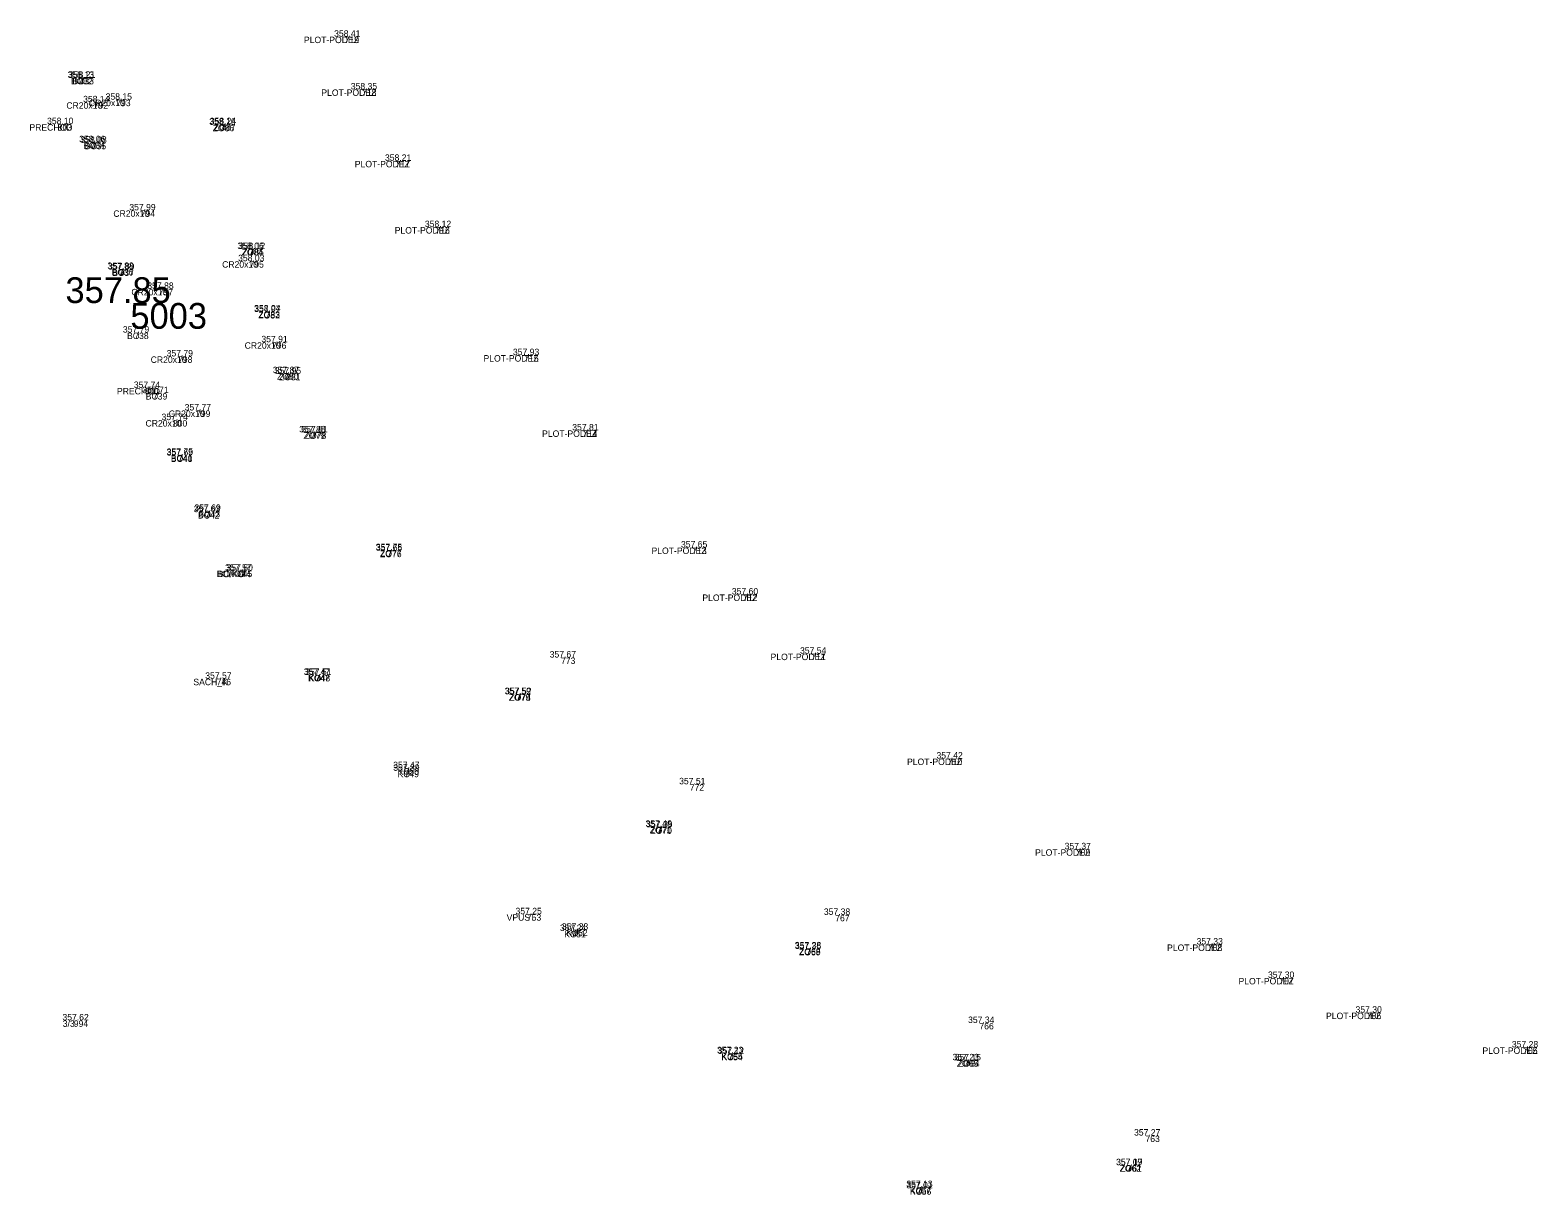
# Model space of a CAD drawing. Extents: x -590413 to -590216, y -1129419 to -1129249.
# Drawn here: x -590268.51 to -590245.08, y -1129323.66 to -1129305.56 of the extents above; entities that cross this region are included whole.
import ezdxf

# ---------------------------------------------------------------- set-up
doc = ezdxf.new("R2010")
doc.units = 0
for name, color, linetype in [('Vrstva B24', 7, 'Continuous'), ('Vrstva B54', 7, 'Continuous'), ('Vrstva B55', 7, 'Continuous'), ('Vrstva B56', 7, 'Continuous'), ('Vrstva B58', 7, 'Continuous'), ('Vrstva B59', 7, 'Continuous'), ('Vrstva B60', 7, 'Continuous')]:
    doc.layers.add(name, color=color, linetype=linetype)

msp = doc.modelspace()

# ---------------------------------------------------------------- linework, layer by layer
at = {"layer": 'Vrstva B56'}
msp.add_line((-590266.95, -1129309.8), (-590266.95, -1129309.8), dxfattribs=at)
at = {"layer": 'Vrstva B60'}
for p, q in [((-590263.62, -1129305.66), (-590263.62, -1129305.66)), ((-590267.76, -1129306.3), (-590267.76, -1129306.3)), ((-590267.74, -1129306.3), (-590267.74, -1129306.3)), ((-590263.35, -1129306.48), (-590263.35, -1129306.48)), ((-590267.52, -1129306.68), (-590267.52, -1129306.68)), ((-590267.17, -1129306.64), (-590267.17, -1129306.64)), ((-590268.08, -1129307.02), (-590268.08, -1129307.02)), ((-590265.56, -1129307.03), (-590265.56, -1129307.03)), ((-590265.54, -1129307.02), (-590265.54, -1129307.02)), ((-590267.57, -1129307.3), (-590267.57, -1129307.3)), ((-590267.55, -1129307.31), (-590267.55, -1129307.31)), ((-590262.83, -1129307.59), (-590262.83, -1129307.59)), ((-590266.79, -1129308.36), (-590266.79, -1129308.36)), ((-590262.21, -1129308.62), (-590262.21, -1129308.62)), ((-590265.11, -1129308.96), (-590265.11, -1129308.96)), ((-590265.1, -1129308.96), (-590265.1, -1129308.96)), ((-590265.1, -1129309.15), (-590265.1, -1129309.15)), ((-590267.13, -1129309.27), (-590267.13, -1129309.27)), ((-590267.12, -1129309.28), (-590267.12, -1129309.28)), ((-590266.51, -1129309.58), (-590266.51, -1129309.58)), ((-590264.85, -1129309.93), (-590264.85, -1129309.93)), ((-590264.85, -1129309.94), (-590264.85, -1129309.94)), ((-590266.89, -1129310.26), (-590266.89, -1129310.26)), ((-590264.75, -1129310.41), (-590264.75, -1129310.41)), ((-590266.21, -1129310.63), (-590266.21, -1129310.63)), ((-590260.83, -1129310.61), (-590260.83, -1129310.61)), ((-590264.56, -1129310.89), (-590264.56, -1129310.89)), ((-590264.53, -1129310.9), (-590264.53, -1129310.9)), ((-590266.72, -1129311.12), (-590266.72, -1129311.12)), ((-590266.6, -1129311.2), (-590266.6, -1129311.2)), ((-590265.93, -1129311.47), (-590265.93, -1129311.47)), ((-590266.29, -1129311.62), (-590266.29, -1129311.62)), ((-590264.15, -1129311.81), (-590264.15, -1129311.81)), ((-590264.13, -1129311.81), (-590264.13, -1129311.81)), ((-590259.92, -1129311.78), (-590259.92, -1129311.78)), ((-590266.21, -1129312.16), (-590266.21, -1129312.16)), ((-590266.21, -1129312.17), (-590266.21, -1129312.17)), ((-590265.79, -1129313.05), (-590265.79, -1129313.05)), ((-590265.78, -1129313.03), (-590265.78, -1129313.03)), ((-590258.22, -1129313.6), (-590258.22, -1129313.6)), ((-590262.96, -1129313.64), (-590262.96, -1129313.64)), ((-590262.96, -1129313.65), (-590262.96, -1129313.65)), ((-590265.3, -1129313.96), (-590265.3, -1129313.96)), ((-590265.28, -1129313.96), (-590265.28, -1129313.96)), ((-590257.43, -1129314.33), (-590257.43, -1129314.33)), ((-590260.26, -1129315.31), (-590260.26, -1129315.31)), ((-590256.37, -1129315.25), (-590256.37, -1129315.25)), ((-590265.61, -1129315.64), (-590265.61, -1129315.64)), ((-590264.08, -1129315.58), (-590264.08, -1129315.58)), ((-590264.07, -1129315.58), (-590264.07, -1129315.58)), ((-590260.96, -1129315.88), (-590260.96, -1129315.88)), ((-590260.95, -1129315.88), (-590260.95, -1129315.88)), ((-590254.25, -1129316.88), (-590254.25, -1129316.88)), ((-590262.69, -1129317.03), (-590262.69, -1129317.03)), ((-590262.69, -1129317.07), (-590262.69, -1129317.07)), ((-590258.26, -1129317.28), (-590258.26, -1129317.28)), ((-590258.77, -1129317.94), (-590258.77, -1129317.94)), ((-590258.76, -1129317.95), (-590258.76, -1129317.95)), ((-590252.26, -1129318.29), (-590252.26, -1129318.29)), ((-590260.79, -1129319.3), (-590260.79, -1129319.3)), ((-590256, -1129319.31), (-590256, -1129319.31)), ((-590260.1, -1129319.56), (-590260.1, -1129319.56)), ((-590260.07, -1129319.54), (-590260.07, -1129319.54)), ((-590256.45, -1129319.83), (-590256.45, -1129319.83)), ((-590256.45, -1129319.84), (-590256.45, -1129319.84)), ((-590250.21, -1129319.77), (-590250.21, -1129319.77)), ((-590249.1, -1129320.29), (-590249.1, -1129320.29)), ((-590247.74, -1129320.83), (-590247.74, -1129320.83)), ((-590267.83, -1129320.95), (-590267.83, -1129320.95)), ((-590253.76, -1129320.99), (-590253.76, -1129320.99)), ((-590257.66, -1129321.46), (-590257.66, -1129321.46)), ((-590257.66, -1129321.47), (-590257.66, -1129321.47)), ((-590245.31, -1129321.37), (-590245.31, -1129321.37)), ((-590254, -1129321.57), (-590254, -1129321.57)), ((-590253.98, -1129321.57), (-590253.98, -1129321.57)), ((-590251.18, -1129322.74), (-590251.18, -1129322.74)), ((-590251.47, -1129323.2), (-590251.47, -1129323.2)), ((-590251.46, -1129323.2), (-590251.46, -1129323.2)), ((-590254.73, -1129323.54), (-590254.73, -1129323.54)), ((-590254.73, -1129323.56), (-590254.73, -1129323.56))]:
    msp.add_line(p, q, dxfattribs=at)

# ---------------------------------------------------------------- texts
at = {"layer": 'Vrstva B24'}
for s, p in [('PLOT-PODEZ', (-590264.254, -1129305.76)), ('BO', (-590267.872, -1129306.4)), ('BO', (-590267.852, -1129306.4)), ('PLOT-PODEZ', (-590263.984, -1129306.58)), ('CR20x10', (-590267.945, -1129306.78)), ('CR20x10', (-590267.595, -1129306.74)), ('PRECHOD', (-590268.519, -1129307.12)), ('ZO', (-590265.672, -1129307.13)), ('ZO', (-590265.652, -1129307.12)), ('BO', (-590267.682, -1129307.4)), ('BO', (-590267.662, -1129307.41)), ('PLOT-PODEZ', (-590263.464, -1129307.69)), ('CR20x10', (-590267.215, -1129308.46)), ('PLOT-PODEZ', (-590262.844, -1129308.72)), ('CR20x10', (-590265.525, -1129309.25)), ('ZO', (-590265.222, -1129309.06)), ('ZO', (-590265.212, -1129309.06)), ('BO', (-590267.242, -1129309.37)), ('BO', (-590267.232, -1129309.38)), ('CR20x10', (-590266.935, -1129309.68)), ('ZO', (-590264.962, -1129310.03)), ('ZO', (-590264.962, -1129310.04)), ('BO', (-590267.002, -1129310.36)), ('CR20x10', (-590265.175, -1129310.51)), ('CR20x10', (-590266.635, -1129310.73)), ('PLOT-PODEZ', (-590261.464, -1129310.71)), ('ZO', (-590264.672, -1129310.99)), ('ZO', (-590264.642, -1129311)), ('PRECHOD', (-590267.159, -1129311.22)), ('BO', (-590266.712, -1129311.3)), ('CR20x10', (-590266.355, -1129311.57)), ('CR20x10', (-590266.715, -1129311.72)), ('ZO', (-590264.262, -1129311.91)), ('ZO', (-590264.242, -1129311.91)), ('PLOT-PODEZ', (-590260.554, -1129311.88)), ('BO', (-590266.322, -1129312.26)), ('BO', (-590266.322, -1129312.27)), ('BO', (-590265.902, -1129313.15)), ('BO', (-590265.892, -1129313.13)), ('PLOT-PODEZ', (-590258.854, -1129313.7)), ('ZO', (-590263.072, -1129313.74)), ('ZO', (-590263.072, -1129313.75)), ('BO/KO', (-590265.613, -1129314.06)), ('BO/KO', (-590265.593, -1129314.06)), ('PLOT-PODEZ', (-590258.064, -1129314.43)), ('PLOT-PODEZ', (-590257.004, -1129315.35)), ('SACH_K', (-590265.972, -1129315.74)), ('KO', (-590264.189, -1129315.68)), ('KO', (-590264.179, -1129315.68)), ('ZO', (-590261.072, -1129315.98)), ('ZO', (-590261.062, -1129315.98)), ('PLOT-PODEZ', (-590254.884, -1129316.98)), ('KO', (-590262.799, -1129317.13)), ('KO', (-590262.799, -1129317.17)), ('ZO', (-590258.882, -1129318.04)), ('ZO', (-590258.872, -1129318.05)), ('PLOT-PODEZ', (-590252.894, -1129318.39)), ('VPUST', (-590261.105, -1129319.4)), ('KO', (-590260.209, -1129319.66)), ('KO', (-590260.179, -1129319.64)), ('ZO', (-590256.562, -1129319.93)), ('ZO', (-590256.562, -1129319.94)), ('PLOT-PODEZ', (-590250.844, -1129319.87)), ('PLOT-PODEZ', (-590249.734, -1129320.39)), ('PLOT-PODEZ', (-590248.374, -1129320.93)), ('3/3', (-590268.001, -1129321.05)), ('KO', (-590257.769, -1129321.56)), ('KO', (-590257.769, -1129321.57)), ('PLOT-PODEZ', (-590245.944, -1129321.47)), ('ZO', (-590254.112, -1129321.67)), ('ZO', (-590254.092, -1129321.67)), ('ZO', (-590251.582, -1129323.3)), ('ZO', (-590251.572, -1129323.3)), ('KO', (-590254.839, -1129323.64)), ('KO', (-590254.839, -1129323.66))]:
    msp.add_text(s, height=0.1, dxfattribs=at).set_placement(p)
at = {"layer": 'Vrstva B54'}
msp.add_text('357.85', height=0.4, dxfattribs=at).set_placement((-590267.959, -1129309.8))
at = {"layer": 'Vrstva B55'}
msp.add_text('5003', height=0.4, dxfattribs=at).set_placement((-590266.95, -1129310.2))
at = {"layer": 'Vrstva B58'}
for s, p in [('358.41', (-590263.785, -1129305.66)), ('358.13', (-590267.925, -1129306.3)), ('358.21', (-590267.905, -1129306.3)), ('358.15', (-590267.335, -1129306.64)), ('358.35', (-590263.526, -1129306.48)), ('358.14', (-590267.685, -1129306.68)), ('358.10', (-590268.245, -1129307.02)), ('358.16', (-590265.725, -1129307.03)), ('358.24', (-590265.717, -1129307.02)), ('358.06', (-590267.747, -1129307.3)), ('358.08', (-590267.727, -1129307.31)), ('358.21', (-590262.995, -1129307.59)), ('357.99', (-590266.967, -1129308.36)), ('358.12', (-590262.375, -1129308.62)), ('358.06', (-590265.287, -1129308.96)), ('358.12', (-590265.265, -1129308.96)), ('358.03', (-590265.277, -1129309.15)), ('357.88', (-590267.307, -1129309.27)), ('357.89', (-590267.297, -1129309.28)), ('357.88', (-590266.687, -1129309.58)), ('358.04', (-590265.027, -1129309.93)), ('357.97', (-590265.027, -1129309.94)), ('357.79', (-590267.067, -1129310.26)), ('357.91', (-590264.915, -1129310.41)), ('357.79', (-590266.387, -1129310.63)), ('357.93', (-590261.007, -1129310.61)), ('357.87', (-590264.737, -1129310.89)), ('357.74', (-590266.897, -1129311.12)), ('357.95', (-590264.707, -1129310.9)), ('357.71', (-590266.765, -1129311.2)), ('357.77', (-590266.107, -1129311.47)), ('357.74', (-590266.467, -1129311.62)), ('357.88', (-590264.327, -1129311.81)), ('357.81', (-590264.295, -1129311.81)), ('357.81', (-590260.085, -1129311.78)), ('357.75', (-590266.387, -1129312.16)), ('357.69', (-590266.386, -1129312.17)), ('357.63', (-590265.966, -1129313.05)), ('357.69', (-590265.956, -1129313.03)), ('357.75', (-590263.137, -1129313.64)), ('357.66', (-590263.136, -1129313.65)), ('357.65', (-590258.396, -1129313.6)), ('357.57', (-590265.477, -1129313.96)), ('357.60', (-590265.456, -1129313.96)), ('357.60', (-590257.606, -1129314.33)), ('357.67', (-590260.436, -1129315.31)), ('357.54', (-590256.547, -1129315.25)), ('357.57', (-590265.787, -1129315.64)), ('357.47', (-590264.257, -1129315.58)), ('357.51', (-590264.235, -1129315.58)), ('357.59', (-590261.137, -1129315.88)), ('357.52', (-590261.127, -1129315.88)), ('357.42', (-590254.427, -1129316.88)), ('357.47', (-590262.867, -1129317.03)), ('357.39', (-590262.866, -1129317.07)), ('357.51', (-590258.425, -1129317.28)), ('357.46', (-590258.947, -1129317.94)), ('357.39', (-590258.936, -1129317.95)), ('357.37', (-590252.436, -1129318.29)), ('357.25', (-590260.967, -1129319.3)), ('357.38', (-590256.176, -1129319.31)), ('357.33', (-590260.246, -1129319.54)), ('357.24', (-590260.277, -1129319.56)), ('357.33', (-590250.386, -1129319.77)), ('357.28', (-590256.627, -1129319.83)), ('357.35', (-590256.626, -1129319.84)), ('357.30', (-590249.276, -1129320.29)), ('357.62', (-590268.006, -1129320.95)), ('357.30', (-590247.916, -1129320.83)), ('357.34', (-590253.936, -1129320.99)), ('357.28', (-590245.487, -1129321.37)), ('357.23', (-590257.837, -1129321.46)), ('357.12', (-590257.825, -1129321.47)), ('357.23', (-590254.177, -1129321.57)), ('357.15', (-590254.145, -1129321.57)), ('357.27', (-590251.357, -1129322.74)), ('357.09', (-590251.637, -1129323.2)), ('357.17', (-590251.635, -1129323.2)), ('357.13', (-590254.895, -1129323.54)), ('357.01', (-590254.895, -1129323.56))]:
    msp.add_text(s, height=0.1, dxfattribs=at).set_placement(p)
at = {"layer": 'Vrstva B59'}
for s, p in [('719', (-590263.62, -1129305.76)), ('732', (-590267.76, -1129306.4)), ('733', (-590267.74, -1129306.4)), ('718', (-590263.35, -1129306.58)), ('792', (-590267.52, -1129306.78)), ('793', (-590267.17, -1129306.74)), ('803', (-590268.08, -1129307.12)), ('786', (-590265.56, -1129307.13)), ('787', (-590265.54, -1129307.12)), ('734', (-590267.57, -1129307.4)), ('735', (-590267.55, -1129307.41)), ('717', (-590262.83, -1129307.69)), ('794', (-590266.79, -1129308.46)), ('716', (-590262.21, -1129308.72)), ('784', (-590265.11, -1129309.06)), ('785', (-590265.1, -1129309.06)), ('795', (-590265.1, -1129309.25)), ('736', (-590267.13, -1129309.37)), ('737', (-590267.12, -1129309.38)), ('797', (-590266.51, -1129309.68)), ('783', (-590264.85, -1129310.03)), ('782', (-590264.85, -1129310.04)), ('738', (-590266.89, -1129310.36)), ('796', (-590264.75, -1129310.51)), ('798', (-590266.21, -1129310.73)), ('715', (-590260.83, -1129310.71)), ('780', (-590264.56, -1129310.99)), ('781', (-590264.53, -1129311)), ('801', (-590266.72, -1129311.22)), ('739', (-590266.6, -1129311.3)), ('799', (-590265.93, -1129311.57)), ('800', (-590266.29, -1129311.72)), ('779', (-590264.15, -1129311.91)), ('778', (-590264.13, -1129311.91)), ('714', (-590259.92, -1129311.88)), ('741', (-590266.21, -1129312.26)), ('740', (-590266.21, -1129312.27)), ('742', (-590265.79, -1129313.15)), ('743', (-590265.78, -1129313.13)), ('713', (-590258.22, -1129313.7)), ('777', (-590262.96, -1129313.74)), ('776', (-590262.96, -1129313.75)), ('744', (-590265.3, -1129314.06)), ('745', (-590265.28, -1129314.06)), ('712', (-590257.43, -1129314.43)), ('773', (-590260.26, -1129315.41)), ('711', (-590256.37, -1129315.35)), ('746', (-590265.61, -1129315.74)), ('747', (-590264.08, -1129315.68)), ('748', (-590264.07, -1129315.68)), ('775', (-590260.96, -1129315.98)), ('774', (-590260.95, -1129315.98)), ('710', (-590254.25, -1129316.98)), ('750', (-590262.69, -1129317.13)), ('749', (-590262.69, -1129317.17)), ('772', (-590258.26, -1129317.38)), ('771', (-590258.77, -1129318.04)), ('770', (-590258.76, -1129318.05)), ('709', (-590252.26, -1129318.39)), ('753', (-590260.79, -1129319.4)), ('767', (-590256, -1129319.41)), ('751', (-590260.1, -1129319.66)), ('752', (-590260.07, -1129319.64)), ('768', (-590256.45, -1129319.93)), ('769', (-590256.45, -1129319.94)), ('708', (-590250.21, -1129319.87)), ('707', (-590249.1, -1129320.39)), ('706', (-590247.74, -1129320.93)), ('994', (-590267.83, -1129321.05)), ('766', (-590253.76, -1129321.09)), ('755', (-590257.66, -1129321.56)), ('754', (-590257.66, -1129321.57)), ('705', (-590245.31, -1129321.47)), ('765', (-590254, -1129321.67)), ('764', (-590253.98, -1129321.67)), ('763', (-590251.18, -1129322.84)), ('762', (-590251.47, -1129323.3)), ('761', (-590251.46, -1129323.3)), ('757', (-590254.73, -1129323.64)), ('756', (-590254.73, -1129323.66))]:
    msp.add_text(s, height=0.1, dxfattribs=at).set_placement(p)

doc.saveas('drawing.dxf')
